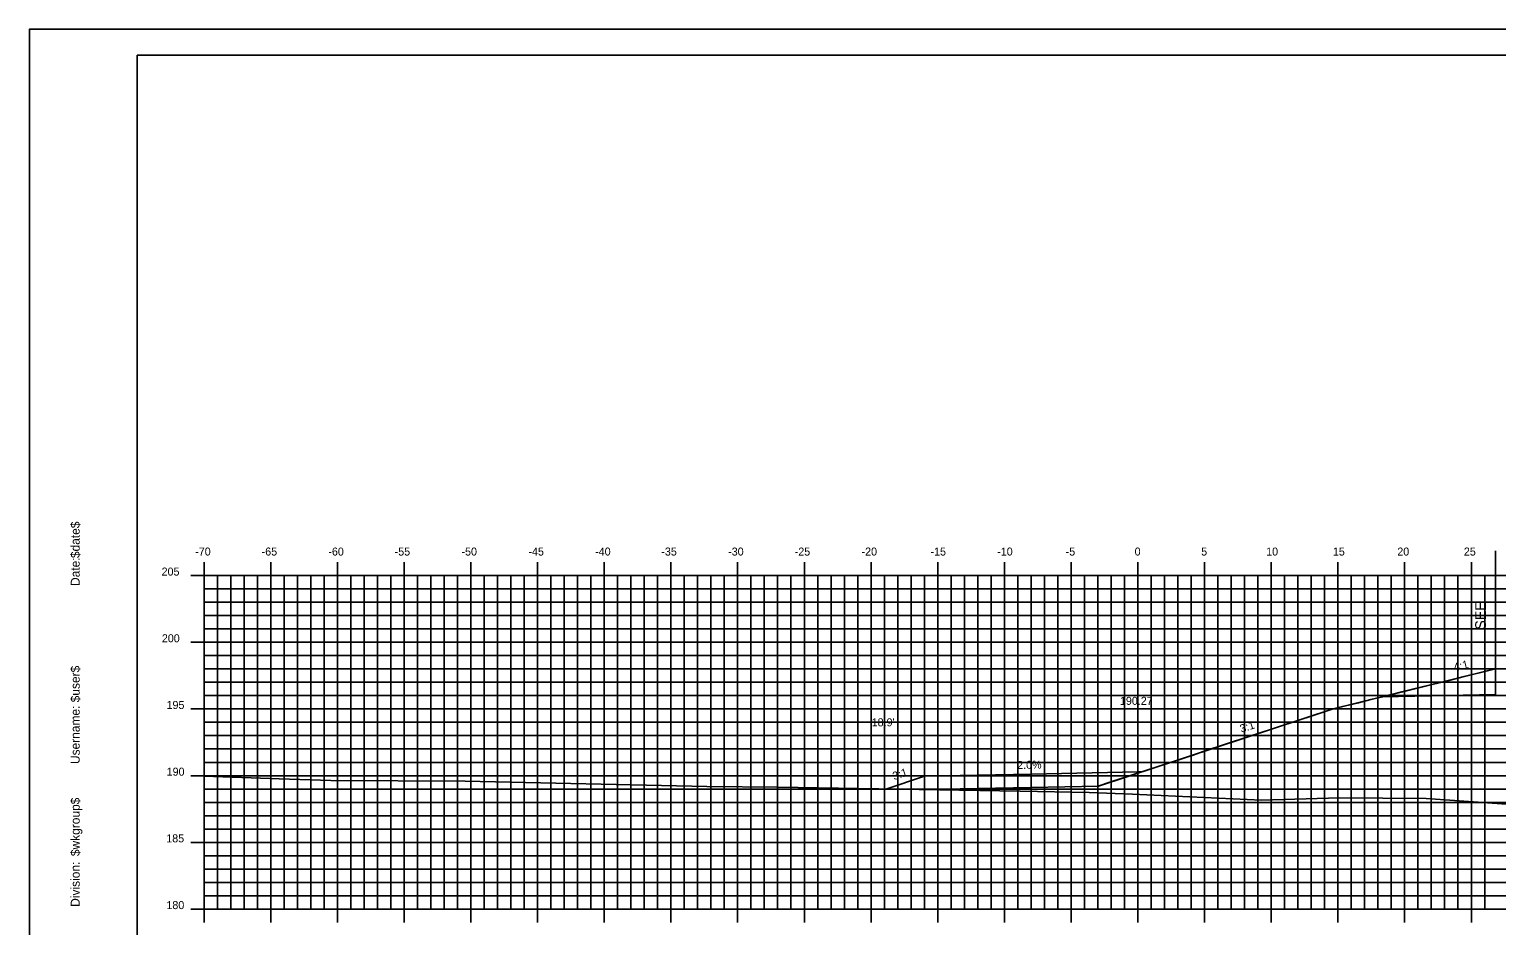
# Model space of a CAD drawing. Extents: x 1723986 to 1724158, y 458501 to 458611.
# Drawn here: x 1723986.2 to 1724096.2, y 458544 to 458611.2 of the extents above; entities that cross this region are included whole.
import ezdxf

# ---------------------------------------------------------------- set-up
doc = ezdxf.new("R2010")
doc.units = 0
for name, color, linetype in [('ANNOTATION', 7, 'Continuous'), ('BORDER', 7, 'Continuous'), ('D_Roadway_Centerline', 7, 'Continuous'), ('D_Roadway_Centerline_Text', 7, 'Continuous'), ('D_Roadway_Drive_Gravel', 7, 'Continuous'), ('D_Roadway_Edge_Shoulder', 7, 'Continuous'), ('D_Roadway_SlopeLines', 7, 'Continuous'), ('D_Roadway_SubGrade', 7, 'Continuous'), ('D_Text_Standard', 7, 'Continuous'), ('H_V ANNOTATION', 7, 'Continuous'), ('MAJOR', 7, 'Continuous'), ('MINOR', 7, 'Continuous'), ('PLOT BOUNDARY', 7, 'Continuous'), ('S_Roadway_Centerline', 7, 'Continuous')]:
    doc.layers.add(name, color=color, linetype=linetype)

msp = doc.modelspace()

# ---------------------------------------------------------------- linework, layer by layer
at = {"layer": 'BORDER'}
msp.add_lwpolyline([(1723994.3, 458504.25), (1724154.3, 458504.25), (1724154.3, 458609.25), (1723994.3, 458609.25)], close=True, dxfattribs=at)
at = {"layer": 'D_Roadway_Centerline'}
msp.add_lwpolyline([(1724066.35, 458554.47), (1724066.39, 458554.49), (1724066.4, 458554.49), (1724067.13, 458554.73), (1724072.82, 458556.6), (1724073.44, 458556.8), (1724074.2, 458557.05), (1724077.62, 458558.18), (1724079.33, 458558.74), (1724081.67, 458559.51), (1724081.99, 458559.61), (1724083.95, 458560.26), (1724084.87, 458560.49), (1724085.83, 458560.72), (1724086.76, 458560.95), (1724087.63, 458561.17), (1724089.1, 458561.53), (1724089.79, 458561.7), (1724091.24, 458562.06), (1724092.33, 458562.32), (1724093.77, 458562.68), (1724096.1, 458563.25)], dxfattribs=at)
at = {"layer": 'D_Roadway_Drive_Gravel'}
msp.add_lwpolyline([(1724069.3, 458555.53), (1724061.3, 458555.37), (1724053.3, 458555.21), (1724050.42, 458554.25), (1724053.3, 458554.21), (1724061.3, 458554.37), (1724066.35, 458554.47)], dxfattribs=at)
at = {"layer": 'D_Roadway_Edge_Shoulder'}
msp.add_line((1724096.1, 458563.25), (1724096.1, 458563), dxfattribs=at)
msp.add_line((1724096.1, 458563.25), (1724096.1, 458563), dxfattribs=at)
at = {"layer": 'D_Roadway_SlopeLines'}
for points in [[(1724096.1, 458563.25), (1724083.95, 458560.26), (1724066.35, 458554.47)], [(1724096.1, 458563.25), (1724083.95, 458560.26), (1724066.35, 458554.47)], [(1724096.1, 458563.25), (1724083.95, 458560.26), (1724066.35, 458554.47)], [(1724096.1, 458563.25), (1724083.95, 458560.26), (1724066.35, 458554.47)], [(1724096.1, 458563.25), (1724083.95, 458560.26), (1724066.35, 458554.47)], [(1724096.1, 458563.25), (1724083.95, 458560.26), (1724066.35, 458554.47)], [(1724096.1, 458563.25), (1724083.95, 458560.26)], [(1724096.1, 458563.25), (1724083.95, 458560.26)], [(1724096.1, 458563.25), (1724087.63, 458561.17)], [(1724069.3, 458555.53), (1724069.59, 458555.53)], [(1724053.3, 458555.21), (1724050.42, 458554.25)]]:
    msp.add_lwpolyline(points, dxfattribs=at)
at = {"layer": 'D_Roadway_SubGrade'}
msp.add_line((1724096.1, 458572.11), (1724096.1, 458561.33), dxfattribs=at)
for points in [[(1724096.1, 458561.33), (1724087.63, 458561.17), (1724096.1, 458563.25), (1724096.1, 458563)], [(1724096.1, 458563), (1724096.1, 458563.25), (1724087.63, 458561.17), (1724096.1, 458561.33)]]:
    msp.add_lwpolyline(points, dxfattribs=at)
at = {"layer": 'MAJOR'}
for p, q in [((1723999.3, 458571.26), (1723999.3, 458570.25)), ((1724004.3, 458571.26), (1724004.3, 458570.25)), ((1724009.3, 458571.26), (1724009.3, 458570.25)), ((1724014.3, 458571.26), (1724014.3, 458570.25)), ((1724019.3, 458571.26), (1724019.3, 458570.25)), ((1724024.3, 458571.26), (1724024.3, 458570.25)), ((1724029.3, 458571.26), (1724029.3, 458570.25)), ((1724034.3, 458571.26), (1724034.3, 458570.25)), ((1724039.3, 458571.26), (1724039.3, 458570.25)), ((1724044.3, 458571.26), (1724044.3, 458570.25)), ((1724049.3, 458571.26), (1724049.3, 458570.25)), ((1724054.3, 458571.26), (1724054.3, 458570.25)), ((1724059.3, 458571.26), (1724059.3, 458570.25)), ((1724064.3, 458571.26), (1724064.3, 458570.25)), ((1724069.3, 458571.26), (1724069.3, 458570.25)), ((1724074.3, 458571.26), (1724074.3, 458570.25)), ((1724079.3, 458571.26), (1724079.3, 458570.25)), ((1724084.3, 458571.26), (1724084.3, 458570.25)), ((1724089.3, 458571.26), (1724089.3, 458570.25)), ((1724094.3, 458571.26), (1724094.3, 458570.25)), ((1723998.3, 458570.25), (1723999.3, 458570.25)), ((1723999.3, 458570.25), (1724139.3, 458570.25)), ((1723999.3, 458545.25), (1723999.3, 458570.25)), ((1723999.3, 458545.25), (1723999.3, 458570.25)), ((1723999.3, 458570.25), (1724139.3, 458570.25)), ((1724004.3, 458545.25), (1724004.3, 458570.25)), ((1724009.3, 458545.25), (1724009.3, 458570.25)), ((1724014.3, 458545.25), (1724014.3, 458570.25)), ((1724019.3, 458545.25), (1724019.3, 458570.25)), ((1724024.3, 458545.25), (1724024.3, 458570.25)), ((1724029.3, 458545.25), (1724029.3, 458570.25)), ((1724034.3, 458545.25), (1724034.3, 458570.25)), ((1724039.3, 458545.25), (1724039.3, 458570.25)), ((1724044.3, 458545.25), (1724044.3, 458570.25)), ((1724049.3, 458545.25), (1724049.3, 458570.25)), ((1724054.3, 458545.25), (1724054.3, 458570.25)), ((1724059.3, 458545.25), (1724059.3, 458570.25)), ((1724064.3, 458545.25), (1724064.3, 458570.25)), ((1724069.3, 458545.25), (1724069.3, 458570.25)), ((1724074.3, 458545.25), (1724074.3, 458570.25)), ((1724079.3, 458545.25), (1724079.3, 458570.25)), ((1724084.3, 458545.25), (1724084.3, 458570.25)), ((1724089.3, 458545.25), (1724089.3, 458570.25)), ((1724094.3, 458545.25), (1724094.3, 458570.25)), ((1723998.3, 458565.25), (1723999.3, 458565.25)), ((1723999.3, 458565.25), (1724139.3, 458565.25)), ((1723998.3, 458560.25), (1723999.3, 458560.25)), ((1723999.3, 458560.25), (1724139.3, 458560.25)), ((1723998.3, 458555.25), (1723999.3, 458555.25)), ((1723999.3, 458555.25), (1724139.3, 458555.25)), ((1723998.3, 458550.25), (1723999.3, 458550.25)), ((1723999.3, 458550.25), (1724139.3, 458550.25)), ((1723998.3, 458545.25), (1723999.3, 458545.25)), ((1723999.3, 458545.25), (1724139.3, 458545.25)), ((1723999.3, 458545.25), (1724139.3, 458545.25)), ((1723999.3, 458544.25), (1723999.3, 458545.25)), ((1724004.3, 458544.25), (1724004.3, 458545.25)), ((1724009.3, 458544.25), (1724009.3, 458545.25)), ((1724014.3, 458544.25), (1724014.3, 458545.25)), ((1724019.3, 458544.25), (1724019.3, 458545.25)), ((1724024.3, 458544.25), (1724024.3, 458545.25)), ((1724029.3, 458544.25), (1724029.3, 458545.25)), ((1724034.3, 458544.25), (1724034.3, 458545.25)), ((1724039.3, 458544.25), (1724039.3, 458545.25)), ((1724044.3, 458544.25), (1724044.3, 458545.25)), ((1724049.3, 458544.25), (1724049.3, 458545.25)), ((1724054.3, 458544.25), (1724054.3, 458545.25)), ((1724059.3, 458544.25), (1724059.3, 458545.25)), ((1724064.3, 458544.25), (1724064.3, 458545.25)), ((1724069.3, 458544.25), (1724069.3, 458545.25)), ((1724074.3, 458544.25), (1724074.3, 458545.25)), ((1724079.3, 458544.25), (1724079.3, 458545.25)), ((1724084.3, 458544.25), (1724084.3, 458545.25)), ((1724089.3, 458544.25), (1724089.3, 458545.25)), ((1724094.3, 458544.25), (1724094.3, 458545.25))]:
    msp.add_line(p, q, dxfattribs=at)
at = {"layer": 'MINOR'}
for p, q in [((1724000.3, 458545.25), (1724000.3, 458570.25)), ((1724001.3, 458545.25), (1724001.3, 458570.25)), ((1724002.3, 458545.25), (1724002.3, 458570.25)), ((1724003.3, 458545.25), (1724003.3, 458570.25)), ((1724005.3, 458545.25), (1724005.3, 458570.25)), ((1724006.3, 458545.25), (1724006.3, 458570.25)), ((1724007.3, 458545.25), (1724007.3, 458570.25)), ((1724008.3, 458545.25), (1724008.3, 458570.25)), ((1724010.3, 458545.25), (1724010.3, 458570.25)), ((1724011.3, 458545.25), (1724011.3, 458570.25)), ((1724012.3, 458545.25), (1724012.3, 458570.25)), ((1724013.3, 458545.25), (1724013.3, 458570.25)), ((1724015.3, 458545.25), (1724015.3, 458570.25)), ((1724016.3, 458545.25), (1724016.3, 458570.25)), ((1724017.3, 458545.25), (1724017.3, 458570.25)), ((1724018.3, 458545.25), (1724018.3, 458570.25)), ((1724020.3, 458545.25), (1724020.3, 458570.25)), ((1724021.3, 458545.25), (1724021.3, 458570.25)), ((1724022.3, 458545.25), (1724022.3, 458570.25)), ((1724023.3, 458545.25), (1724023.3, 458570.25)), ((1724025.3, 458545.25), (1724025.3, 458570.25)), ((1724026.3, 458545.25), (1724026.3, 458570.25)), ((1724027.3, 458545.25), (1724027.3, 458570.25)), ((1724028.3, 458545.25), (1724028.3, 458570.25)), ((1724030.3, 458545.25), (1724030.3, 458570.25)), ((1724031.3, 458545.25), (1724031.3, 458570.25)), ((1724032.3, 458545.25), (1724032.3, 458570.25)), ((1724033.3, 458545.25), (1724033.3, 458570.25)), ((1724035.3, 458545.25), (1724035.3, 458570.25)), ((1724036.3, 458545.25), (1724036.3, 458570.25)), ((1724037.3, 458545.25), (1724037.3, 458570.25)), ((1724038.3, 458545.25), (1724038.3, 458570.25)), ((1724040.3, 458545.25), (1724040.3, 458570.25)), ((1724041.3, 458545.25), (1724041.3, 458570.25)), ((1724042.3, 458545.25), (1724042.3, 458570.25)), ((1724043.3, 458545.25), (1724043.3, 458570.25)), ((1724045.3, 458545.25), (1724045.3, 458570.25)), ((1724046.3, 458545.25), (1724046.3, 458570.25)), ((1724047.3, 458545.25), (1724047.3, 458570.25)), ((1724048.3, 458545.25), (1724048.3, 458570.25)), ((1724050.3, 458545.25), (1724050.3, 458570.25)), ((1724051.3, 458545.25), (1724051.3, 458570.25)), ((1724052.3, 458545.25), (1724052.3, 458570.25)), ((1724053.3, 458545.25), (1724053.3, 458570.25)), ((1724055.3, 458545.25), (1724055.3, 458570.25)), ((1724056.3, 458545.25), (1724056.3, 458570.25)), ((1724057.3, 458545.25), (1724057.3, 458570.25)), ((1724058.3, 458545.25), (1724058.3, 458570.25)), ((1724060.3, 458545.25), (1724060.3, 458570.25)), ((1724061.3, 458545.25), (1724061.3, 458570.25)), ((1724062.3, 458545.25), (1724062.3, 458570.25)), ((1724063.3, 458545.25), (1724063.3, 458570.25)), ((1724065.3, 458545.25), (1724065.3, 458570.25)), ((1724066.3, 458545.25), (1724066.3, 458570.25)), ((1724067.3, 458545.25), (1724067.3, 458570.25)), ((1724068.3, 458545.25), (1724068.3, 458570.25)), ((1724070.3, 458545.25), (1724070.3, 458570.25)), ((1724071.3, 458545.25), (1724071.3, 458570.25)), ((1724072.3, 458545.25), (1724072.3, 458570.25)), ((1724073.3, 458545.25), (1724073.3, 458570.25)), ((1724075.3, 458545.25), (1724075.3, 458570.25)), ((1724076.3, 458545.25), (1724076.3, 458570.25)), ((1724077.3, 458545.25), (1724077.3, 458570.25)), ((1724078.3, 458545.25), (1724078.3, 458570.25)), ((1724080.3, 458545.25), (1724080.3, 458570.25)), ((1724081.3, 458545.25), (1724081.3, 458570.25)), ((1724082.3, 458545.25), (1724082.3, 458570.25)), ((1724083.3, 458545.25), (1724083.3, 458570.25)), ((1724085.3, 458545.25), (1724085.3, 458570.25)), ((1724086.3, 458545.25), (1724086.3, 458570.25)), ((1724087.3, 458545.25), (1724087.3, 458570.25)), ((1724088.3, 458545.25), (1724088.3, 458570.25)), ((1724090.3, 458545.25), (1724090.3, 458570.25)), ((1724091.3, 458545.25), (1724091.3, 458570.25)), ((1724092.3, 458545.25), (1724092.3, 458570.25)), ((1724093.3, 458545.25), (1724093.3, 458570.25)), ((1724095.3, 458545.25), (1724095.3, 458570.25)), ((1723999.3, 458569.25), (1724139.3, 458569.25)), ((1723999.3, 458569.25), (1724000.3, 458569.25)), ((1723999.3, 458568.25), (1724139.3, 458568.25)), ((1723999.3, 458568.25), (1724000.3, 458568.25)), ((1723999.3, 458567.25), (1724139.3, 458567.25)), ((1723999.3, 458567.25), (1724000.3, 458567.25)), ((1723999.3, 458566.25), (1724139.3, 458566.25)), ((1723999.3, 458566.25), (1724000.3, 458566.25)), ((1723999.3, 458564.25), (1724139.3, 458564.25)), ((1723999.3, 458564.25), (1724000.3, 458564.25)), ((1723999.3, 458563.25), (1724139.3, 458563.25)), ((1723999.3, 458563.25), (1724000.3, 458563.25)), ((1723999.3, 458562.25), (1724139.3, 458562.25)), ((1723999.3, 458562.25), (1724000.3, 458562.25)), ((1723999.3, 458561.25), (1724139.3, 458561.25)), ((1723999.3, 458561.25), (1724000.3, 458561.25)), ((1723999.3, 458559.25), (1724139.3, 458559.25)), ((1723999.3, 458559.25), (1724000.3, 458559.25)), ((1723999.3, 458558.25), (1724139.3, 458558.25)), ((1723999.3, 458558.25), (1724000.3, 458558.25)), ((1723999.3, 458557.25), (1724139.3, 458557.25)), ((1723999.3, 458557.25), (1724000.3, 458557.25)), ((1723999.3, 458556.25), (1724139.3, 458556.25)), ((1723999.3, 458556.25), (1724000.3, 458556.25)), ((1723999.3, 458554.25), (1724139.3, 458554.25)), ((1723999.3, 458554.25), (1724000.3, 458554.25)), ((1723999.3, 458553.25), (1724139.3, 458553.25)), ((1723999.3, 458553.25), (1724000.3, 458553.25)), ((1723999.3, 458552.25), (1724139.3, 458552.25)), ((1723999.3, 458552.25), (1724000.3, 458552.25)), ((1723999.3, 458551.25), (1724139.3, 458551.25)), ((1723999.3, 458551.25), (1724000.3, 458551.25)), ((1723999.3, 458549.25), (1724139.3, 458549.25)), ((1723999.3, 458549.25), (1724000.3, 458549.25)), ((1723999.3, 458548.25), (1724139.3, 458548.25)), ((1723999.3, 458548.25), (1724000.3, 458548.25)), ((1723999.3, 458547.25), (1724139.3, 458547.25)), ((1723999.3, 458547.25), (1724000.3, 458547.25)), ((1723999.3, 458546.25), (1724139.3, 458546.25)), ((1723999.3, 458546.25), (1724000.3, 458546.25))]:
    msp.add_line(p, q, dxfattribs=at)
at = {"layer": 'PLOT BOUNDARY'}
msp.add_lwpolyline([(1723986.21, 458501.2), (1724156.21, 458501.2), (1724156.21, 458611.2), (1723986.21, 458611.2)], close=True, dxfattribs=at)
at = {"layer": 'S_Roadway_Centerline'}
msp.add_lwpolyline([(1723999.3, 458555.22), (1724004.93, 458555.02), (1724008.8, 458554.9), (1724018.87, 458554.84), (1724037, 458554.45), (1724042.32, 458554.38), (1724060.47, 458554.09), (1724065.64, 458554), (1724068.91, 458553.87), (1724078.57, 458553.42), (1724084.41, 458553.6), (1724090.91, 458553.55), (1724101.53, 458552.78), (1724103.05, 458552.67), (1724113.96, 458552.58), (1724122.9, 458552.15), (1724127.48, 458551.88), (1724135.52, 458551.54), (1724138.83, 458551.43), (1724139.3, 458551.41)], dxfattribs=at)

# ---------------------------------------------------------------- texts
at = {"layer": 'ANNOTATION'}
for s, height, rotation, p in [('SEE', 0.8, 90, (1724095.39, 458566.19)), ('4:1', 0.6, 13.6162, (1724093.05, 458563.07)), ('3:1', 0.6, 18.4349, (1724077.06, 458558.46)), ('3:1', 0.6, 18.4349, (1724051.03, 458554.91)), ('2.0%', 0.6, 1.1458, (1724060.26, 458555.75))]:
    msp.add_text(s, height=height, rotation=rotation, dxfattribs=at).set_placement(p)
at = {"layer": 'BORDER'}
for s, p in [('$date$', (1723989.98, 458571.56)), ('Date:', (1723989.98, 458569.47)), ('$user$', (1723989.98, 458560.75)), ('Username:', (1723989.98, 458556.12)), ('$wkgroup$', (1723989.98, 458549.22)), ('Division:', (1723989.98, 458545.42))]:
    msp.add_text(s, height=0.67, rotation=90, dxfattribs=at).set_placement(p)
at = {"layer": 'D_Roadway_Centerline_Text'}
msp.add_text('190.27', height=0.6, dxfattribs=at).set_placement((1724067.96, 458560.56))
at = {"layer": 'D_Text_Standard'}
msp.add_text("18.9'", height=0.6, dxfattribs=at).set_placement((1724049.35, 458558.95))
at = {"layer": 'H_V ANNOTATION'}
for s, p in [('-70', (1723998.64, 458571.75)), ('-65', (1724003.62, 458571.75)), ('-60', (1724008.62, 458571.75)), ('-55', (1724013.59, 458571.75)), ('-50', (1724018.6, 458571.75)), ('-45', (1724023.62, 458571.75)), ('-40', (1724028.62, 458571.75)), ('-35', (1724033.58, 458571.75)), ('-30', (1724038.59, 458571.75)), ('-25', (1724043.58, 458571.75)), ('-20', (1724048.59, 458571.75)), ('-15', (1724053.76, 458571.75)), ('-10', (1724058.76, 458571.75)), ('-5', (1724063.89, 458571.75)), ('0', (1724069.06, 458571.75)), ('5', (1724074.05, 458571.75)), ('10', (1724078.92, 458571.75)), ('15', (1724083.92, 458571.75)), ('20', (1724088.75, 458571.75)), ('25', (1724093.74, 458571.75)), ('205', (1723996.12, 458570.25)), ('200', (1723996.14, 458565.25)), ('195', (1723996.49, 458560.25)), ('190', (1723996.5, 458555.25)), ('185', (1723996.47, 458550.25)), ('180', (1723996.48, 458545.25))]:
    msp.add_text(s, height=0.6, dxfattribs=at).set_placement(p)
at = {"layer": 'MAJOR'}
msp.add_text('-', height=0.006, dxfattribs=at).set_placement((1723999.29, 458545.25))

doc.saveas('drawing.dxf')
